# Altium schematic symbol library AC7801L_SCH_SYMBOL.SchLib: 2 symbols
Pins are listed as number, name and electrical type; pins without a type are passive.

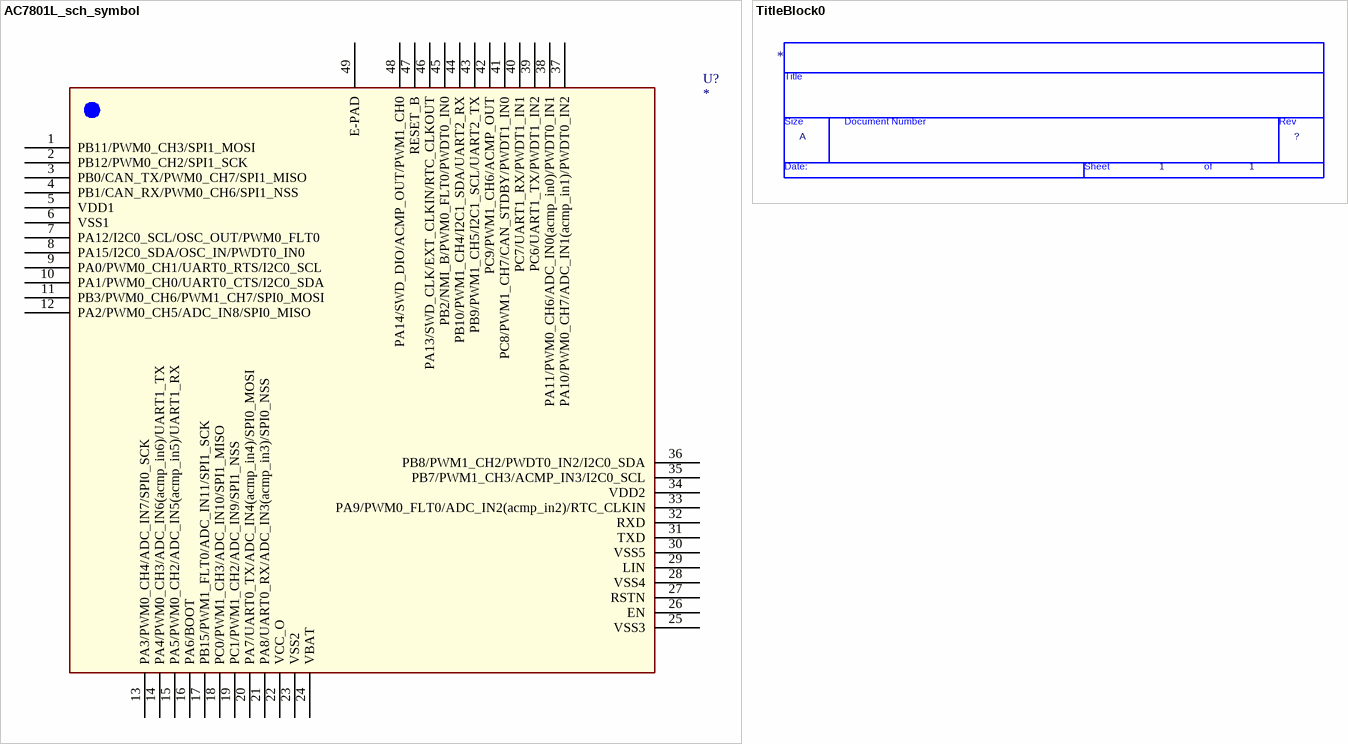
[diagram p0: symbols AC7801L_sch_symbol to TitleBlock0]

## AC7801L_sch_symbol
designator U?
footprint LQFP80/SMD
pins: 1 PB11/PWM0_CH3/SPI1_MOSI, 2 PB12/PWM0_CH2/SPI1_SCK, 3 PB0/CAN_TX/PWM0_CH7/SPI1_MISO, 4 PB1/CAN_RX/PWM0_CH6/SPI1_NSS, 5 VDD1, 6 VSS1, 7 PA12/I2C0_SCL/OSC_OUT/PWM0_FLT0, 8 PA15/I2C0_SDA/OSC_IN/PWDT0_IN0, 9 PA0/PWM0_CH1/UART0_RTS/I2C0_SCL, 10 PA1/PWM0_CH0/UART0_CTS/I2C0_SDA, 11 PB3/PWM0_CH6/PWM1_CH7/SPI0_MOSI, 12 PA2/PWM0_CH5/ADC_IN8/SPI0_MISO, 13 PA3/PWM0_CH4/ADC_IN7/SPI0_SCK, 14 PA4/PWM0_CH3/ADC_IN6(acmp_in6)/UART1_TX, 15 PA5/PWM0_CH2/ADC_IN5(acmp_in5)/UART1_RX, 16 PA6/BOOT, 17 PB15/PWM1_FLT0/ADC_IN11/SPI1_SCK, 18 PC0/PWM1_CH3/ADC_IN10/SPI1_MISO, 19 PC1/PWM1_CH2/ADC_IN9/SPI1_NSS, 20 PA7/UART0_TX/ADC_IN4(acmp_in4)/SPI0_MOSI, 21 PA8/UART0_RX/ADC_IN3(acmp_in3)/SPI0_NSS, 22 VCC_O, 23 VSS2, 24 VBAT, 25 VSS3, 26 EN, 27 RSTN, 28 VSS4, 29 LIN, 30 VSS5, 31 TXD, 32 RXD, 33 PA9/PWM0_FLT0/ADC_IN2(acmp_in2)/RTC_CLKIN, 34 VDD2, 35 PB7/PWM1_CH3/ACMP_IN3/I2C0_SCL, 36 PB8/PWM1_CH2/PWDT0_IN2/I2C0_SDA, 37 PA10/PWM0_CH7/ADC_IN1(acmp_in1)/PWDT0_IN2, 38 PA11/PWM0_CH6/ADC_IN0(acmp_in0)/PWDT0_IN1, 39 PC6/UART1_TX/PWDT1_IN2, 40 PC7/UART1_RX/PWDT1_IN1, 41 PC8/PWM1_CH7/CAN_STDBY/PWDT1_IN0, 42 PC9/PWM1_CH6/ACMP_OUT, 43 PB9/PWM1_CH5/I2C1_SCL/UART2_TX, 44 PB10/PWM1_CH4/I2C1_SDA/UART2_RX, 45 PB2/NMI_B/PWM0_FLT0/PWDT0_IN0, 46 PA13/SWD_CLK/EXT_CLKIN/RTC_CLKOUT, 47 RESET_B, 48 PA14/SWD_DIO/ACMP_OUT/PWM1_CH0, 49 E-PAD

## TitleBlock0
designator *  Page Count: 1  Page Size: A  (graphical)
